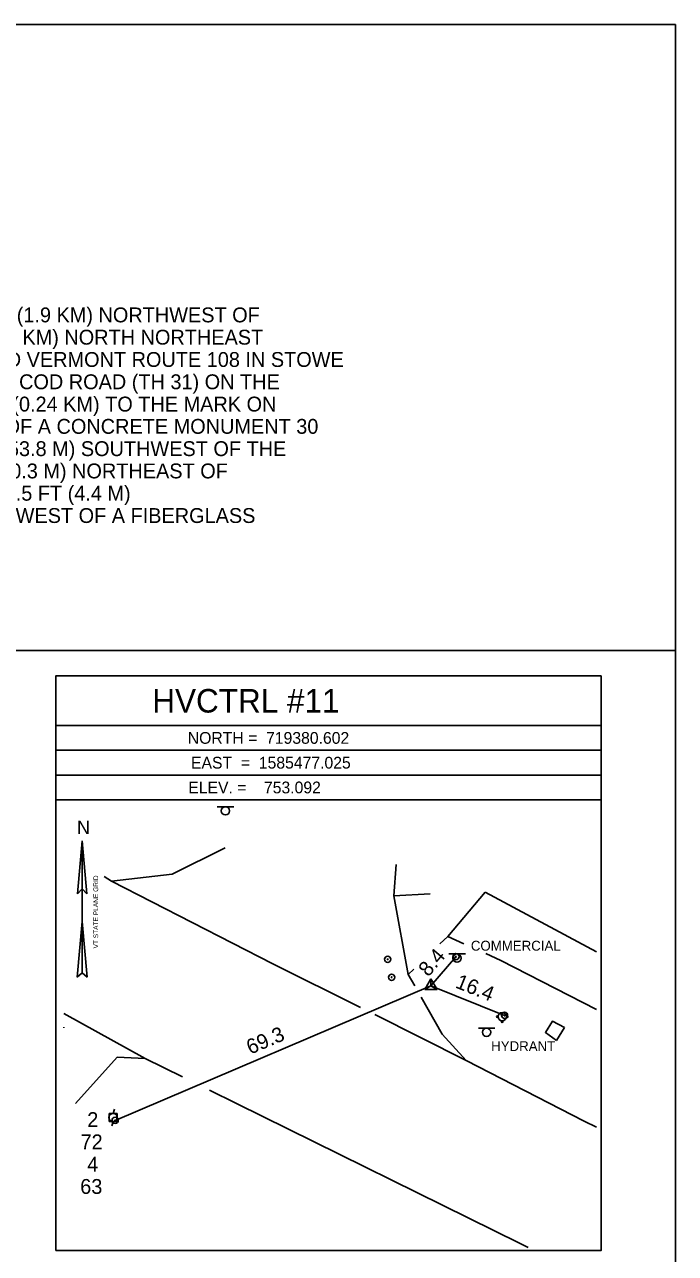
# Model space of a CAD drawing. Extents: x 1584895 to 1585535, y 718730 to 719150.
# Drawn here: x 1585403.6 to 1585534.9, y 718901.7 to 719149.7 of the extents above; entities that cross this region are included whole.
import ezdxf

# ---------------------------------------------------------------- set-up
doc = ezdxf.new("R2010")
doc.units = 0
for name, color, linetype in [('C_C', 7, 'Continuous'), ('CBP', 7, 'Continuous'), ('CPSM', 7, 'Continuous'), ('Level 1', 7, 'Continuous'), ('Level 2', 7, 'Continuous'), ('LS', 7, 'Continuous'), ('NBL1', 7, 'Continuous'), ('NBL2', 7, 'Continuous'), ('PET', 7, 'Continuous'), ('RDP', 7, 'Continuous'), ('RSW', 7, 'Continuous'), ('S_C', 7, 'Continuous'), ('SSGN', 7, 'Continuous'), ('U_C', 7, 'Continuous'), ('UP', 7, 'Continuous'), ('UWFH', 7, 'Continuous'), ('UWV', 7, 'Continuous')]:
    doc.layers.add(name, color=color, linetype=linetype)

msp = doc.modelspace()

# ---------------------------------------------------------------- linework, layer by layer
at = {"layer": 'CBP'}
for centre, radius in [((1585490.62, 718961.56), 0.625), ((1585490.62, 718961.56), 0.0833), ((1585500.43, 718949.71), 0.625), ((1585500.43, 718949.71), 0.0833), ((1585421.87, 718928.52), 0.625), ((1585421.87, 718928.52), 0.0833)]:
    msp.add_circle(centre, radius, dxfattribs=at)
at = {"layer": 'CPSM'}
for p, q in [((1585484.32, 718954.94), (1585485.57, 718957.11)), ((1585486.82, 718954.94), (1585485.57, 718957.11)), ((1585485.57, 718955.66), (1585485.57, 718957.11)), ((1585484.32, 718954.94), (1585485.57, 718955.66)), ((1585484.32, 718954.94), (1585486.82, 718954.94)), ((1585485.57, 718955.66), (1585485.57, 718955.66)), ((1585485.57, 718955.66), (1585486.82, 718954.94))]:
    msp.add_line(p, q, dxfattribs=at)
at = {"layer": 'Level 1'}
for p, q in [((1585414.26, 718974.23), (1585415.21, 718984.92)), ((1585415.22, 718958.34), (1585415.21, 718984.92)), ((1585416.17, 718974.23), (1585415.21, 718984.92)), ((1585414.26, 718974.23), (1585415.22, 718975.28)), ((1585416.17, 718974.23), (1585415.22, 718975.28)), ((1585415.22, 718968.66), (1585414.23, 718957.46)), ((1585415.22, 718968.66), (1585416.21, 718957.46)), ((1585415.22, 718958.34), (1585414.23, 718957.46)), ((1585415.22, 718958.34), (1585416.21, 718957.46))]:
    msp.add_line(p, q, dxfattribs=at)
at = {"layer": 'Level 2'}
for p, q in [((1585485.57, 718955.66), (1585490.62, 718961.56)), ((1585421.87, 718928.52), (1585485.57, 718955.66)), ((1585485.57, 718955.66), (1585500.43, 718949.71))]:
    msp.add_line(p, q, dxfattribs=at)
at = {"layer": 'LS'}
for points in [[(1585512.54, 718947.3), (1585510.08, 718948.52), (1585508.68, 718946.28), (1585510.91, 718944.64)], [(1585512.54, 718947.3), (1585510.91, 718944.64)]]:
    msp.add_lwpolyline(points, dxfattribs=at)
at = {"layer": 'NBL1'}
msp.add_lwpolyline([(1584894.9, 718729.73), (1585534.9, 718729.73), (1585534.9, 719149.73), (1584894.9, 719149.73)], close=True, dxfattribs=at)
at = {"layer": 'NBL2'}
for p, q in [((1584894.9, 719023.39), (1585534.9, 719023.39)), ((1585519.9, 719008.23), (1585409.9, 719008.23)), ((1585519.9, 719003.23), (1585409.9, 719003.23)), ((1585519.9, 718998.23), (1585409.9, 718998.23)), ((1585519.9, 718993.23), (1585409.9, 718993.23))]:
    msp.add_line(p, q, dxfattribs=at)
msp.add_lwpolyline([(1585409.9, 718902.23), (1585519.9, 718902.23), (1585519.9, 719018.23), (1585409.9, 719018.23)], close=True, dxfattribs=at)
at = {"layer": 'PET'}
for points in [[(1585421.14, 718976.82), (1585433.4, 718978.2), (1585444.07, 718983.55)], [(1585478.55, 718980.15), (1585478.11, 718973.82), (1585480.98, 718957.97), (1585482.3, 718955.65)], [(1585419.62, 718977.75), (1585421.14, 718976.82), (1585453.7, 718960.15), (1585471.39, 718951.3)], [(1585483.58, 718953.4), (1585487.84, 718945.94), (1585492.71, 718940.63)], [(1585411.49, 718950.1), (1585427.95, 718940.99), (1585435.44, 718937.31)], [(1585474.25, 718949.87), (1585492.71, 718940.63), (1585516.5, 718928.38), (1585518.98, 718927.17)], [(1585440.93, 718934.61), (1585446.37, 718931.94), (1585503.59, 718903.64), (1585505.21, 718902.84)]]:
    msp.add_lwpolyline(points, dxfattribs=at)
at = {"layer": 'RDP'}
for points in [[(1585496.53, 718974.57), (1585518.98, 718962.53)], [(1585488.98, 718965.65), (1585492.21, 718964.19)], [(1585496.62, 718962.18), (1585499.69, 718960.78), (1585518.98, 718950.91)], [(1585411.49, 718947.32), (1585411.51, 718947.28), (1585411.49, 718947.22)], [(1585413.9, 718931.94), (1585422.28, 718941.25), (1585427.95, 718940.99)]]:
    msp.add_lwpolyline(points, dxfattribs=at)
at = {"layer": 'RSW'}
for points in [[(1585478.11, 718973.82), (1585485.39, 718974.23)], [(1585487.4, 718964.14), (1585488.98, 718965.65), (1585496.53, 718974.57)], [(1585480.98, 718957.97), (1585482.13, 718959.08)]]:
    msp.add_lwpolyline(points, dxfattribs=at)
at = {"layer": 'SSGN'}
for p, q in [((1585442.48, 718991.85), (1585445.81, 718991.85)), ((1585444.12, 718991.01), (1585444.12, 718991.01)), ((1585489.19, 718962.11), (1585492.52, 718962.11)), ((1585490.83, 718961.28), (1585490.83, 718961.28)), ((1585495.15, 718947.14), (1585498.49, 718947.14)), ((1585496.8, 718946.31), (1585496.8, 718946.31))]:
    msp.add_line(p, q, dxfattribs=at)
for centre in [(1585444.12, 718991.01), (1585490.83, 718961.28), (1585496.8, 718946.31)]:
    msp.add_circle(centre, 0.833, dxfattribs=at)
at = {"layer": 'UP'}
for p, q in [((1585420.63, 718928.27), (1585420.63, 718929.93)), ((1585420.63, 718929.93), (1585422.29, 718929.93)), ((1585421.71, 718930.77), (1585421.46, 718929.93)), ((1585422.29, 718929.93), (1585422.29, 718928.27)), ((1585422.29, 718928.27), (1585420.63, 718928.27)), ((1585421.21, 718927.43), (1585421.46, 718928.27)), ((1585421.46, 718929.1), (1585421.46, 718929.1))]:
    msp.add_line(p, q, dxfattribs=at)
msp.add_circle((1585421.46, 718929.1), 0.833, dxfattribs=at)
at = {"layer": 'UWFH'}
msp.add_line((1585499.96, 718949.46), (1585499.96, 718949.46), dxfattribs=at)
for centre, radius in [((1585498.96, 718949.46), 0.167), ((1585499.96, 718949.46), 0.833), ((1585500.96, 718949.46), 0.167), ((1585499.96, 718948.46), 0.167)]:
    msp.add_circle(centre, radius, dxfattribs=at)
at = {"layer": 'UWV'}
for centre, radius in [((1585476.85, 718961.04), 0.625), ((1585476.85, 718961.04), 0.0833), ((1585477.65, 718957.41), 0.625), ((1585477.65, 718957.41), 0.0833)]:
    msp.add_circle(centre, radius, dxfattribs=at)

# ---------------------------------------------------------------- texts
at = {"layer": 'C_C'}
msp.add_text('HYDRANT', height=2, dxfattribs=at).set_placement((1585497.73, 718942.51))
at = {"layer": 'Level 1'}
msp.add_text('N', height=2.71, dxfattribs=at).set_placement((1585414.17, 718986.31))
msp.add_text('VT STATE PLANE GRID', height=0.9604, rotation=90.0204, dxfattribs=at).set_placement((1585418.44, 718963.23))
at = {"layer": 'Level 2'}
for s, p in [('GENERAL LOCATION - THE STATION IS LOCATED IN THE TOWN OF STOWE, 1.2 MI(1.9 KM) NORTHWEST OF ', (1585242.65, 719089.62)), ('STOWE VILLAGE, 8.1 MI (13.0 KM) SOUTHWEST OF MORRISVILLE, AND 9.8 MI (15.8 KM) NORTH NORTHEAST ', (1585242.65, 719085.12)), ('OF WATERBURY.  TO REACH FROM THE JUNCTION OF VERMONT ROUTE 100 AND VERMONT ROUTE 108 IN STOWE ', (1585242.65, 719080.62)), ('VILLAGE, PROCEED NORTHERLY ALONG ROUTE 108 FOR 1.7 MI (2.7 KM)TO CAPE COD ROAD (TH 31) ON THE ', (1585242.65, 719076.12)), ('RIGHT.  TURN RIGHT AND GO NORTHEAST ALONG CAPE COD ROAD FOR 0.15 MI (0.24 KM) TO THE MARK ON ', (1585242.65, 719071.62)), ('THE RIGHT. THE MARK IS A STATE OF VERMONT SURVEY DISK SET IN THE TOP OF A CONCRETE MONUMENT 30 ', (1585242.65, 719067.12)), ('CM IN DIAMETER FLUSH WITH THE GROUND SURFACE. IT IS LOCATED 176.5 FT (53.8 M) SOUTHWEST OF THE ', (1585242.65, 719062.62)), ('CENTERLINE OF A PAVED DRIVE TO VILLAGE GREEN CONDOMINIUMS, 66.5 FT (20.3 M) NORTHEAST OF ', (1585242.65, 719058.12)), ('UTILITY POLE 3, 31.5 FT (9.6 M) NORTH OF A HIGHWAY SIGN (SPEED LIMIT 35) , 14.5 FT (4.4 M) ', (1585242.65, 719053.62)), ('SOUTHEAST OF THE CENTERLINE OF CAPE COD ROAD (TH 31) , AND 1 FT (0.3 M) WEST OF A FIBERGLASS ', (1585242.65, 719049.12))]:
    msp.add_text(s, height=3, dxfattribs=at).set_placement(p)
for s, rotation, p in [('8.4', 49.4548, (1585485.05, 718957.36)), ('16.4', 338.1677, (1585490.32, 718955.38)), ('69.3', 23.075, (1585449.14, 718941.77))]:
    msp.add_text(s, height=3, rotation=rotation, dxfattribs=at).set_placement(p)
at = {"layer": 'NBL2'}
for s, height, p in [('     HVCTRL #11    ', 4.75, (1585420.54, 719010.85)), ('NORTH =  719380.602 ', 2.375, (1585436.52, 719004.54)), ('EAST  =  1585477.025', 2.375, (1585437.17, 718999.54)), ('ELEV. =    753.092  ', 2.375, (1585436.62, 718994.54))]:
    msp.add_text(s, height=height, dxfattribs=at).set_placement(p)
at = {"layer": 'S_C'}
msp.add_text('COMMERCIAL', height=2, dxfattribs=at).set_placement((1585493.63, 718962.78))
at = {"layer": 'U_C'}
for s, p in [('2', (1585416.24, 718927.18)), ('72', (1585414.89, 718922.68)), ('4', (1585416.24, 718918.18)), ('63', (1585414.82, 718913.68))]:
    msp.add_text(s, height=3, dxfattribs=at).set_placement(p)

doc.saveas('drawing.dxf')
